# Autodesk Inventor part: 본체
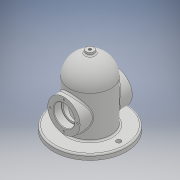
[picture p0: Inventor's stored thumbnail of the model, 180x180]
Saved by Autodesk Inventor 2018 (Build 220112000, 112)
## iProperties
Created: 2019-11
Part Number: 본체
Material: 일반
Document SubType Name: Modeling
Designer: USER
Density: 1 g/cm^3
Appearance: 기본값
Author: USER
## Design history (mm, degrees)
sketch "스케치3"
  geometry: C1 r 31 at (0, 0); 1 further point
  constraints: 1 centre point, 1 coincident
  dimensions: "d3" = 62 diameter of C1
extrude "돌출2" new body sketch "스케치3" stored distance "d4" = 100; taper "d5" = 0 deg
node "작업 평면1"
sketch "스케치5"
  geometry: C1 r 70 at (0, 0); 1 further point
  constraints: 1 centre point, 1 coincident
  dimensions: "d7" = 140 diameter of C1
extrude "돌출3" join sketch "스케치5" distance "d8" = 10; taper "d9" = 0 deg
sketch "스케치6"
  geometry: L1 (70, -40)-(-70, -40) reference; L2 (0, -40)-(-40, -40); L3 (-40, -40)-(-40, 40); L4 (-40, 40)-(0, 40); L5 (0, 40)-(0, -40); L6 (0, 40)-(0, 80); L7 (0, 40)-(-40, 40); L8 (0, 67.168)-(0, -67.168); 2 further points
  constraints: 14 end point, 3 midpoint, 2 horizontal, 2 parallel, 2 vertical, 1 perpendicular
  dimensions: "d10" = 80 distance of L2.end L3.end; "d11" = 40 distance of L3.end L4.end
revolve "회전1" sketch "스케치6" stored, may be unused: angle "d15" = 90 deg
sketch "스케치7"
  geometry: L1 (40, 40)-(-40, 40) reference; L2 (0, 82.045)-(0, -82.045); L3 (0, 40)-(-40, 40); L4 (0, 40)-(0, 80); A1 r 40 centre (0, 40) between (0, 80) and (-40, 40); 2 further points
  constraints: 6 end point, 2 midpoint, 2 point on circle, 2 point on line, 2 vertical, 1 centre point, 1 coincident, 1 horizontal
revolve "회전2" sketch "스케치7" stored, may be unused: angle "d16" = 90 deg
node "작업 평면2"
sketch "스케치8"
  geometry: C1 r 40 at (0, 0) reference; C2 r 7.5 at (0, 0); 1 further point
  constraints: 1 centre point, 1 coincident
  dimensions: "d18" = 15 diameter of C2
extrude "돌출4" join sketch "스케치8" stored distance "d19" = 10; taper "d20" = 0 deg
sketch "스케치9"
  geometry: C1 r 16.5 at (0, 0); 1 further point
  constraints: 1 centre point, 1 coincident
  dimensions: "d21" = 33 diameter of C1
extrude "돌출5" cut sketch "스케치9" extent not by distance; stored distance "d22" = 10; taper "d23" = 0 deg
sketch "스케치10"
  geometry: C1 r 20 at (0, 0); 1 further point
  constraints: 1 centre point, 1 coincident
  dimensions: "d24" = 40 diameter of C1
extrude "돌출6" cut sketch "스케치10" distance "d25" = 15; taper "d26" = 0 deg
sketch "스케치12"
  geometry: L1 (0, 40)-(-30, 40); L2 (-30, 40)-(-30, -50); L3 (-30, -50)-(0, -50); L4 (0, -50)-(0, 40); L5 (0, 126.817)-(0, -126.817); L6 (-70, -50)-(70, -50) reference; 2 further points
  constraints: 10 end point, 2 midpoint, 2 parallel, 1 coincident, 1 horizontal, 1 perpendicular, 1 vertical
  dimensions: "d37" = 30 distance of L1.start L1.end; "d38" = 90 distance of L1.end L2.end
revolve "회전3" sketch "스케치12" stored, may be unused: angle "d39" = 90 deg
sketch "스케치13"
  geometry: L1 (30, 40)-(-30, 40) reference; L2 (0, 40)-(0, 70); L3 (0, 40)-(-30, 40); L4 (0, 70)-(0, 40); L5 (0, 40)-(-30, 40); L6 (0, 99.673)-(0, -99.673); A1 r 30 centre (0, 40) between (0, 70) and (-30, 40); 2 further points
  constraints: 10 end point, 2 midpoint, 2 point on circle, 1 centre point, 1 coincident, 1 vertical
  dimensions: "d40" = 90 deg angle of L2 L3
revolve "회전4" sketch "스케치13" stored, may be unused: angle "d41" = 90 deg
sketch "스케치15"
  geometry: C1 r 7.5 at (0, 0) reference; C2 r 7.5 at (0, 0) reference; 2 further points
  constraints: 1 coincident
hole "구멍1" sketch "스케치15" at (0, 0) diameter "d42" = 5.188; stored, may be unused: countersink angle "d46" = 90 deg, drill point angle "d48" = 118 deg; dims "d43" = 30, "d44" = 4, "d45" = 2, "d47" = 30
sketch "스케치16"
  geometry: 2 further points
  constraints: 1 vertical alignment
  dimensions: "d49" = 26 distance of point (0, 0) point (0, 26)
hole "구멍2" sketch "스케치16" at (0, 26) diameter "d50" = 3.242; stored, may be unused: countersink angle "d54" = 90 deg, drill point angle "d56" = 118 deg; dims "d51" = 8, "d52" = 4, "d53" = 2, "d55" = 10
sketch "스케치17"
  geometry: C1 r 55 at (0, 0); C2 r 4.5 at (-55, 0); C3 r 4.5 at (55, 0); 1 further point
  constraints: 3 centre point, 2 horizontal alignment, 1 coincident
  dimensions: "d60" = 110 diameter of C1; "d61" = 9 diameter of C2; "d62" = 9 diameter of C3; "d63" = 55 distance of point (0, 0) C2.centre; "d64" = 55 distance of point (0, 0) C3.centre
extrude "돌출7" cut sketch "스케치17" distance "d65" = 15; taper "d66" = 0 deg
fillet "모깎기1" dims "d67" = 0.3
chamfer "모따기1" distance "d68" = 1; stored, may be unused: second distance "d69" = 2, angle "d70" = 45 deg
fillet "모깎기2" dims "d71" = 3
fillet "모깎기3" dims "d72" = 3
fillet "모깎기4" dims "d73" = 3
fillet "모깎기5" dims "d74" = 3
node "솔리드2"
mirror "미러1"
pattern_circular "원형 패턴1" dims angle "d58" = 360 deg
mirror "미러2"
other parameters: "d17" = -135
